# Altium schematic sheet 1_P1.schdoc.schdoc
size 309 x 223 mm; Symbol: Sheet-Symbol_A4; Device: Sheet-Symbol_A4; @Project Name: flex_ir_golf; @Page Count: 1; @Update Date: 2024-07-07; @Create Date: 2024-04-06; @Schematic Name: Schematic1; @Page No: 1; @Page Name: P1; Company: EasyEDA.com; Reviewed: EasyEDA; Version: V0.1; Page Size: A4; Part Number: JLCPCB-002; Drawn: EasyEDA
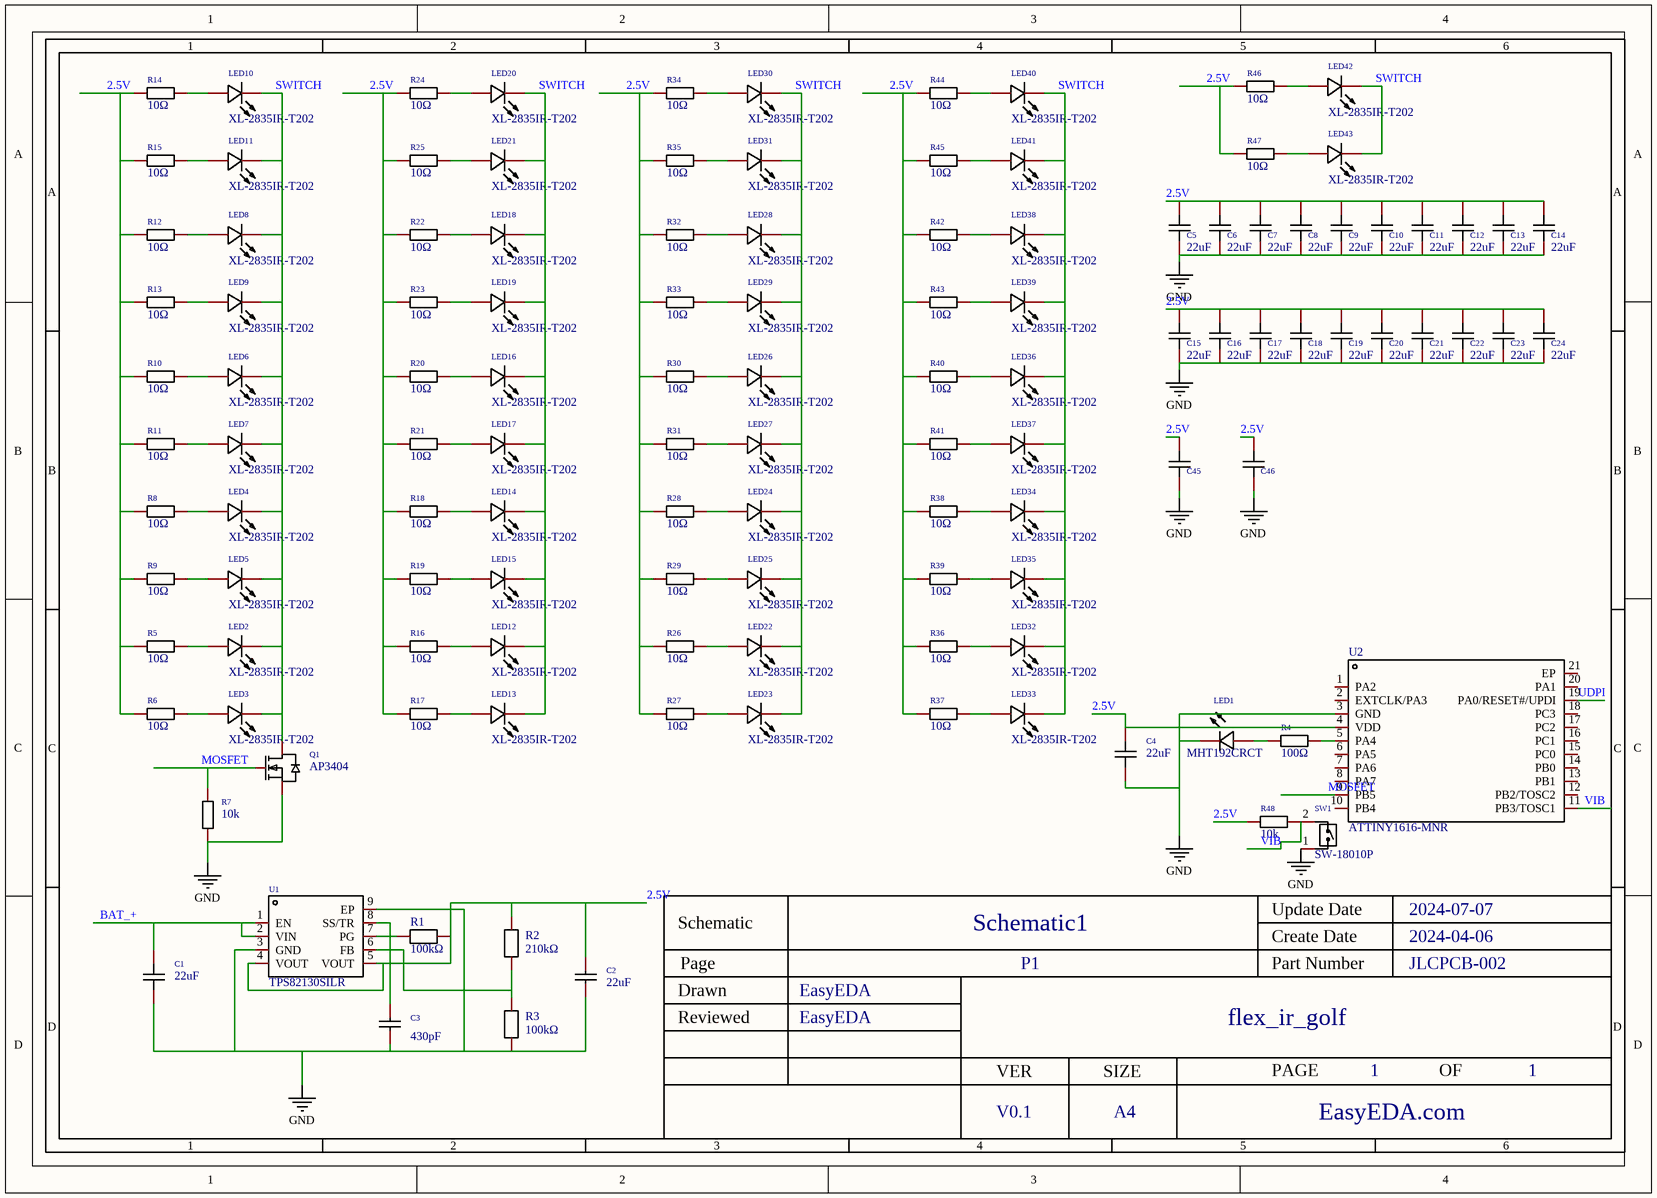
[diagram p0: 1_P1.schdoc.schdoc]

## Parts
C1  22uF  [C0603]
C2  22uF  [C0805]
C3  430pF  [C0402]
C4  22uF  [C0603]
C5  22uF  [C0603]
C6  22uF  [C0603]
C7  22uF  [C0603]
C8  22uF  [C0603]
C9  22uF  [C0603]
C10  22uF  [C0603]
C11  22uF  [C0603]
C12  22uF  [C0603]
C13  22uF  [C0603]
C14  22uF  [C0603]
C15  22uF  [C0603]
C16  22uF  [C0603]
C17  22uF  [C0603]
C18  22uF  [C0603]
C19  22uF  [C0603]
C20  22uF  [C0603]
C21  22uF  [C0603]
C22  22uF  [C0603]
C23  22uF  [C0603]
C24  22uF  [C0603]
C45  22uF  [C0603]  (value not drawn)
C46  22uF  [C0603]  (value not drawn)
LED1  MHT192CRCT  [LED0603-RD]
LED2  XL-2835IR-T202  [LED-SMD_L128-XX80CB3500001]
LED3  XL-2835IR-T202  [LED-SMD_L128-XX80CB3500001]
LED4  XL-2835IR-T202  [LED-SMD_L128-XX80CB3500001]
LED5  XL-2835IR-T202  [LED-SMD_L128-XX80CB3500001]
LED6  XL-2835IR-T202  [LED-SMD_L128-XX80CB3500001]
LED7  XL-2835IR-T202  [LED-SMD_L128-XX80CB3500001]
LED8  XL-2835IR-T202  [LED-SMD_L128-XX80CB3500001]
LED9  XL-2835IR-T202  [LED-SMD_L128-XX80CB3500001]
LED10  XL-2835IR-T202  [LED-SMD_L128-XX80CB3500001]
LED11  XL-2835IR-T202  [LED-SMD_L128-XX80CB3500001]
LED12  XL-2835IR-T202  [LED-SMD_L128-XX80CB3500001]
LED13  XL-2835IR-T202  [LED-SMD_L128-XX80CB3500001]
LED14  XL-2835IR-T202  [LED-SMD_L128-XX80CB3500001]
LED15  XL-2835IR-T202  [LED-SMD_L128-XX80CB3500001]
LED16  XL-2835IR-T202  [LED-SMD_L128-XX80CB3500001]
LED17  XL-2835IR-T202  [LED-SMD_L128-XX80CB3500001]
LED18  XL-2835IR-T202  [LED-SMD_L128-XX80CB3500001]
LED19  XL-2835IR-T202  [LED-SMD_L128-XX80CB3500001]
LED20  XL-2835IR-T202  [LED-SMD_L128-XX80CB3500001]
LED21  XL-2835IR-T202  [LED-SMD_L128-XX80CB3500001]
LED22  XL-2835IR-T202  [LED-SMD_L128-XX80CB3500001]
LED23  XL-2835IR-T202  [LED-SMD_L128-XX80CB3500001]
LED24  XL-2835IR-T202  [LED-SMD_L128-XX80CB3500001]
LED25  XL-2835IR-T202  [LED-SMD_L128-XX80CB3500001]
LED26  XL-2835IR-T202  [LED-SMD_L128-XX80CB3500001]
LED27  XL-2835IR-T202  [LED-SMD_L128-XX80CB3500001]
LED28  XL-2835IR-T202  [LED-SMD_L128-XX80CB3500001]
LED29  XL-2835IR-T202  [LED-SMD_L128-XX80CB3500001]
LED30  XL-2835IR-T202  [LED-SMD_L128-XX80CB3500001]
LED31  XL-2835IR-T202  [LED-SMD_L128-XX80CB3500001]
LED32  XL-2835IR-T202  [LED-SMD_L128-XX80CB3500001]
LED33  XL-2835IR-T202  [LED-SMD_L128-XX80CB3500001]
LED34  XL-2835IR-T202  [LED-SMD_L128-XX80CB3500001]
LED35  XL-2835IR-T202  [LED-SMD_L128-XX80CB3500001]
LED36  XL-2835IR-T202  [LED-SMD_L128-XX80CB3500001]
LED37  XL-2835IR-T202  [LED-SMD_L128-XX80CB3500001]
LED38  XL-2835IR-T202  [LED-SMD_L128-XX80CB3500001]
LED39  XL-2835IR-T202  [LED-SMD_L128-XX80CB3500001]
LED40  XL-2835IR-T202  [LED-SMD_L128-XX80CB3500001]
LED41  XL-2835IR-T202  [LED-SMD_L128-XX80CB3500001]
LED42  XL-2835IR-T202  [LED-SMD_L128-XX80CB3500001]
LED43  XL-2835IR-T202  [LED-SMD_L128-XX80CB3500001]
Q1  AP3404  [SOT-23-3_L2.9-W1.3-P1.90-LS2.4-BR-2]
R1  100kΩ  [R0402]
R2  210kΩ  [R0402]
R3  100kΩ  [R0402]
R4  100Ω  [R0402]
R5  10Ω  [R0603]
R6  10Ω  [R0603]
R7  10k  [R0603]
R8  10Ω  [R0603]
R9  10Ω  [R0603]
R10  10Ω  [R0603]
R11  10Ω  [R0603]
R12  10Ω  [R0603]
R13  10Ω  [R0603]
R14  10Ω  [R0603]
R15  10Ω  [R0603]
R16  10Ω  [R0603]
R17  10Ω  [R0603]
R18  10Ω  [R0603]
R19  10Ω  [R0603]
R20  10Ω  [R0603]
R21  10Ω  [R0603]
R22  10Ω  [R0603]
R23  10Ω  [R0603]
R24  10Ω  [R0603]
R25  10Ω  [R0603]
R26  10Ω  [R0603]
R27  10Ω  [R0603]
R28  10Ω  [R0603]
R29  10Ω  [R0603]
R30  10Ω  [R0603]
R31  10Ω  [R0603]
R32  10Ω  [R0603]
R33  10Ω  [R0603]
R34  10Ω  [R0603]
R35  10Ω  [R0603]
R36  10Ω  [R0603]
R37  10Ω  [R0603]
R38  10Ω  [R0603]
R39  10Ω  [R0603]
R40  10Ω  [R0603]
R41  10Ω  [R0603]
R42  10Ω  [R0603]
R43  10Ω  [R0603]
R44  10Ω  [R0603]
R45  10Ω  [R0603]
R46  10Ω  [R0603]
R47  10Ω  [R0603]
R48  10k  [R0603]
SW1  SW-18010P  [SW-TH_SW-18010P]
U1  TPS82130SILR  [USIP-8_L3.0-W2.8-P0.65-TL-EP]
U2  ATTINY1616-MNR  [QFN-20_L3.0-W3.0-P0.40-BL-EP1.7]

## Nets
GND: C1.1 C2.1 C3.1 C4.1 C5.1 C6.1 C7.1 C8.1 C9.1 C10.1 C11.1 C12.1 C13.1 C14.1 C15.1 C16.1 C17.1 C18.1 C19.1 C20.1 C21.1 C22.1 C23.1 C24.1 C45.1 C46.1 LED1.1(-) Q1.1(S) R3.1 R7.1 SW1.1 U1.3(GND) U1.9(EP) U2.3(GND)
2.5V: C2.2 C4.2 C5.2 C6.2 C7.2 C8.2 C9.2 C10.2 C11.2 C12.2 C13.2 C14.2 C15.2 C16.2 C17.2 C18.2 C19.2 C20.2 C21.2 C22.2 C23.2 C24.2 C45.2 C46.2 R1.2 R2.2 R5.1 R6.1 R8.1 R9.1 R10.1 R11.1 R12.1 R13.1 R14.1 R15.1 R16.1 R17.1 R18.1 R19.1 R20.1 R21.1 R22.1 R23.1 R24.1 R25.1 R26.1 R27.1 R28.1 R29.1 R30.1 R31.1 R32.1 R33.1 R34.1 R35.1 R36.1 R37.1 R38.1 R39.1 R40.1 R41.1 R42.1 R43.1 R44.1 R45.1 R46.1 R47.1 R48.2 U1.4(VOUT) U1.5(VOUT) U2.4(VDD)
BAT_+: C1.2 U1.1(EN) U1.2(VIN)
MOSFET: Q1.2(G) R7.2 U2.9(PB5)
SWITCH: LED2.1(C) LED3.1(C) LED4.1(C) LED5.1(C) LED6.1(C) LED7.1(C) LED8.1(C) LED9.1(C) LED10.1(C) LED11.1(C) LED12.1(C) LED13.1(C) LED14.1(C) LED15.1(C) LED16.1(C) LED17.1(C) LED18.1(C) LED19.1(C) LED20.1(C) LED21.1(C) LED22.1(C) LED23.1(C) LED24.1(C) LED25.1(C) LED26.1(C) LED27.1(C) LED28.1(C) LED29.1(C) LED30.1(C) LED31.1(C) LED32.1(C) LED33.1(C) LED34.1(C) LED35.1(C) LED36.1(C) LED37.1(C) LED38.1(C) LED39.1(C) LED40.1(C) LED41.1(C) LED42.1(C) LED43.1(C) Q1.3(D)
UDPI: U2.19(PA0/RESET#/UPDI)
VIB: R48.1 SW1.2 U2.11(PB3/TOSC1)
NetC3_2: C3.2 U1.8(SS/TR)
NetLED1_2: LED1.2(+) R4.1
NetLED2_2: LED2.2(A) R5.2
NetLED3_2: LED3.2(A) R6.2
NetLED4_2: LED4.2(A) R8.2
NetLED5_2: LED5.2(A) R9.2
NetLED6_2: LED6.2(A) R10.2
NetLED7_2: LED7.2(A) R11.2
NetLED8_2: LED8.2(A) R12.2
NetLED9_2: LED9.2(A) R13.2
NetLED10_2: LED10.2(A) R14.2
NetLED11_2: LED11.2(A) R15.2
NetLED12_2: LED12.2(A) R16.2
NetLED13_2: LED13.2(A) R17.2
NetLED14_2: LED14.2(A) R18.2
NetLED15_2: LED15.2(A) R19.2
NetLED16_2: LED16.2(A) R20.2
NetLED17_2: LED17.2(A) R21.2
NetLED18_2: LED18.2(A) R22.2
NetLED19_2: LED19.2(A) R23.2
NetLED20_2: LED20.2(A) R24.2
NetLED21_2: LED21.2(A) R25.2
NetLED22_2: LED22.2(A) R26.2
NetLED23_2: LED23.2(A) R27.2
NetLED24_2: LED24.2(A) R28.2
NetLED25_2: LED25.2(A) R29.2
NetLED26_2: LED26.2(A) R30.2
NetLED27_2: LED27.2(A) R31.2
NetLED28_2: LED28.2(A) R32.2
NetLED29_2: LED29.2(A) R33.2
NetLED30_2: LED30.2(A) R34.2
NetLED31_2: LED31.2(A) R35.2
NetLED32_2: LED32.2(A) R36.2
NetLED33_2: LED33.2(A) R37.2
NetLED34_2: LED34.2(A) R38.2
NetLED35_2: LED35.2(A) R39.2
NetLED36_2: LED36.2(A) R40.2
NetLED37_2: LED37.2(A) R41.2
NetLED38_2: LED38.2(A) R42.2
NetLED39_2: LED39.2(A) R43.2
NetLED40_2: LED40.2(A) R44.2
NetLED41_2: LED41.2(A) R45.2
NetLED42_2: LED42.2(A) R46.2
NetLED43_2: LED43.2(A) R47.2
NetR1_1: R1.1 U1.7(PG)
NetR2_1: R2.1 R3.2 U1.6(FB)
NetR4_2: R4.2 U2.5(PA4)

Not connected (* = marked no-connect by the designer): U2 1(PA2) 2(EXTCLK/PA3) 6(PA5) 7(PA6) 8(PA7) 10(PB4) 12(PB2/TOSC2) 13(PB1) 14(PB0) 15(PC0) 16(PC1) 17(PC2) 18(PC3) 20(PA1) 21(EP)

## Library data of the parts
C1 C4-C24 C45 C46 = GRM188R60J226MEA0D: Manufacturer: muRata(村田); Add into BOM: yes; Tolerance: ±20%; Description: Capacitance: Tolerance:±20% Tolerance:±20% Voltage Rated: Temperature Coefficient:
C2 = GRM21BR60J226ME39L: Manufacturer: muRata(村田); Add into BOM: yes; Tolerance: ±20%; Description: Capacitance: Tolerance:±20% Tolerance:±20% Voltage Rated: Temperature Coefficient:
C3 = CL05A105KP5NNNC: Manufacturer Part: GRM1555C1H431GA01D; Value: 1uF; Add into BOM: yes; Tolerance: ±10%; Description: Capacitance: Tolerance:±10% Tolerance:±10% Voltage Rated: Temperature Coefficient:
LED1 = MHT192CRCT: Manufacturer: MEIHUA(美华); Add into BOM: yes; Emitted Color: Red; Power Dissipation: 60mW; Forward Current: 5mA; Dominant Wavelength: 621.5nm~633.5nm; Peak Wavelength: 639nm; Lens Color: 无色透明透镜; Viewing Angle: 120°; Description: Emitted Color:Red Power Dissipation:60mW Forward Current:5mA Dominant Wavelength:621.5nm~633.5nm Dominant Wavelength:621.5nm~633.5nm Peak Wavelength:639nm Diode Configuration:- Lens Color:无色透明透镜 Color Temperature:- Color Temperature:- Viewing Angle:120° M
LED2-LED43 = L128-4080CB3500001_C358168: Emitted Color:White; Manufacturer: Lumileds(亮锐); Add into BOM: yes; Emitted Color: IR
Q1 = AP3404: Manufacturer: ALLPOWER(铨力); Add into BOM: yes; Drain Source On Resistance (RDS(on)@Vgs,Id): 18mΩ@10V,5.8A; Gate Threshold Voltage (Vgs(th)@Id): 1.6V@250uA; Input Capacitance (Ciss@Vds): 345pF@15V; Reverse Transfer Capacitance (Crss@Vds): 32pF@15V; Description: Type: Drain Source Voltage (Vdss): Continuous Drain Current (Id): Power Dissipation (Pd): Drain Source On Resistance (RDS(on)@Vgs,Id):18mΩ@10V,5.8A Gate Threshold Voltage (Vgs(th)@Id):1.6V@250uA Total Gate Charge (Qg@Vgs):- Input Capacitance (Ciss@Vds):34
R1 R3 = CRCW0402100KFKED: Manufacturer: VISHAY(威世); Add into BOM: yes; Tolerance: ±1%; Temperature Coefficient: ±100ppm/℃; Description: Type:Thick Film Resistors Resistance: Tolerance:±1% Tolerance:±1% Power(Watts): Overload Voltage (Max): Temperature Coefficient:±100ppm/℃ Temperature Coefficient:±100ppm/℃ Operating Temperature Range:-55℃~+155℃ Operating Temperature Range:-55℃~+155℃
R2 = CRCW0402210KFKED: Manufacturer: VISHAY(威世); Add into BOM: yes; Tolerance: ±1%; Temperature Coefficient: ±100ppm/℃; Description: Type:Thick Film Resistors Resistance: Tolerance:±1% Tolerance:±1% Power(Watts): Overload Voltage (Max): Temperature Coefficient:±100ppm/℃ Temperature Coefficient:±100ppm/℃ Operating Temperature Range:-55℃~+155℃ Operating Temperature Range:-55℃~+155℃
R4 = 0402WGF1000TCE: Manufacturer: UNI-ROYAL(厚声); Add into BOM: yes; Tolerance: ±1%; Temperature Coefficient: ±200ppm/℃; Description: Type:Thick Film Resistors Resistance: Tolerance:±1% Tolerance:±1% Power(Watts): Overload Voltage (Max): Temperature Coefficient:±200ppm/℃ Temperature Coefficient:±200ppm/℃ Operating Temperature Range:-55℃~+155℃ Operating Temperature Range:-55℃~+155℃
R5-R48 = 0603WAF100JT5E: Manufacturer: UNI-ROYAL(厚声); Add into BOM: yes; Tolerance: ±1%; Temperature Coefficient: ±400ppm/℃; Description: Type:Thick Film Resistors Resistance:10Ω Tolerance:±1% Tolerance:±1% Power(Watts): Overload Voltage (Max): Temperature Coefficient:±400ppm/℃ Temperature Coefficient:±400ppm/℃ Operating Temperature Range:-55℃~+155℃ Operating Temperature Range:-55℃~+155℃
SW1 = SW-18010P: Manufacturer: SHOU HAN(首韩); Add into BOM: yes; Rated Voltage: 12V; Rated Current: 20mA; Operating Life: 100万次; Description: Sensor Type:- Rated Voltage:12V Rated Current:20mA Operating Life:100万次 Temperature Resistance:- Temperature Resistance:-
U1 = TPS82130SILR: Manufacturer: TI(德州仪器); Add into BOM: yes; Input Voltage(DC): 3V~17V; Output Voltage: 900mV~6V; Output Current (Max): 3A; Output Channel: 1; Description: Input Voltage(DC):3V~17V Input Voltage(DC):3V~17V Output Voltage:900mV~6V Output Voltage:900mV~6V Output Current (Max):3A Output Current (Max):3A Function:- Output Channel:1
U2 = ATTINY1616-MNR: Manufacturer: MICROCHIP(美国微芯); Add into BOM: yes; CPU Core: AVR; Program Storage Size: 16KB; RAM Size: 2KB; GPIO Ports Number: 18; Operating Voltage Range: 1.8V~5.5V; CPU Maximum Speed: 20MHz; Program Memory Type: FLASH; ADC (Bit): 10bit; DAC (Bit): 8bit; Peripheral/Function: WDT；PWM; Watchdog: 有; Description: CPU Core:AVR Program Storage Size:16KB RAM Size:2KB GPIO Ports Number:18 Operating Voltage Range:1.8V~5.5V Operating Voltage Range:1.8V~5.5V CPU Maximum Speed:20MHz Program Memory Type:FLASH Operating Temperature Range:-40℃~+105℃ Operating Temperature Ran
